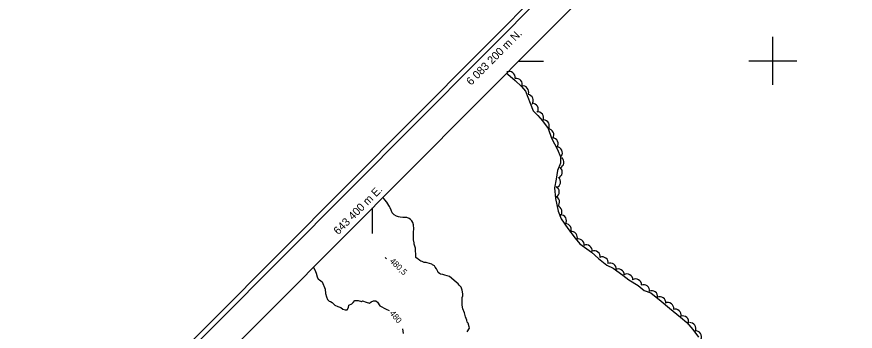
# Model space of a CAD drawing. Extents: x 642515 to 647219, y 6080136 to 6084356.
# Drawn here: x 643222.3 to 643641.3, y 6083064.9 to 6083222.3 of the extents above; entities that cross this region are included whole.
import ezdxf

# ---------------------------------------------------------------- set-up
doc = ezdxf.new("R2010")
doc.units = 0
for name, color, linetype in [('Level 1', 7, 'Continuous'), ('Level 3', 7, 'Continuous'), ('Level 4', 7, 'Continuous'), ('Level 44', 7, 'Continuous'), ('Level 60', 7, 'Continuous'), ('Level 61', 7, 'Continuous')]:
    doc.layers.add(name, color=color, linetype=linetype)

msp = doc.modelspace()

# ---------------------------------------------------------------- linework, layer by layer
at = {"layer": 'Level 1'}
for points in [[(643432.93, 6083094.31), (643432.66, 6083094.86), (643432.03, 6083096.06), (643431.42, 6083096.92), (643430.98, 6083097.64), (643430.06, 6083098.16), (643429.64, 6083098.39), (643427.4, 6083099.17), (643426.82, 6083099.23), (643425.84, 6083099.34), (643424.84, 6083099.78), (643424.26, 6083100), (643423.75, 6083100.3), (643422.82, 6083100.99), (643422.32, 6083101.29), (643421.72, 6083101.83), (643421.64, 6083103.62), (643421.58, 6083104.93), (643421.51, 6083106.39), (643420.93, 6083108.49), (643420.9, 6083109.14), (643420.58, 6083110.68), (643420.49, 6083112.63), (643420.58, 6083114.43), (643420.67, 6083116.07), (643420.49, 6083118.1), (643420.28, 6083119.23), (643419.66, 6083120.1), (643418.98, 6083120.72), (643418.39, 6083121.26), (643417.14, 6083121.77), (643415.17, 6083121.84), (643413.86, 6083121.94), (643413.04, 6083122.06), (643412.04, 6083122.5), (643410.94, 6083123.18), (643409.92, 6083124.11), (643409.45, 6083125.48), (643408.91, 6083126.6), (643408.55, 6083127.23), (643408.28, 6083127.79), (643407.15, 6083129.45), (643406.19, 6083130.63), (643405.75, 6083131.34), (643405.18, 6083131.86)], [(643370.55, 6083097.02), (643370.64, 6083096.85), (643371.27, 6083095.66), (643371.84, 6083093.89), (643372.41, 6083092.13), (643372.95, 6083091.01), (643373.63, 6083090.55), (643374.98, 6083089.64), (643376.38, 6083085.87), (643376.64, 6083083.76), (643377.04, 6083082.15), (643377.59, 6083080.71), (643378.36, 6083080.01), (643379.03, 6083079.72), (643379.95, 6083079.2), (643380.63, 6083078.58), (643381.31, 6083077.96), (643382.73, 6083077.29), (643384.23, 6083076.71), (643385.25, 6083075.95), (643386.41, 6083075.52), (643387.46, 6083075.65), (643387.99, 6083076.74), (643388.18, 6083077.97), (643389.78, 6083078.54), (643390.4, 6083079.22), (643391.25, 6083080.33), (643391.58, 6083080.34), (643392.89, 6083080.24), (643394.54, 6083079.84), (643395.1, 6083080.11), (643396.85, 6083079.46), (643398.58, 6083078.98), (643399.45, 6083079.59), (643400.5, 6083080.05), (643401.72, 6083080.03), (643402.57, 6083079.42), (643403.79, 6083077.68), (643406.89, 6083075.96), (643408.31, 6083075.23)], [(643447.42, 6083064.59), (643448.57, 6083066.36), (643448.37, 6083067.16), (643447.8, 6083068.93), (643447.36, 6083069.48), (643447.24, 6083070.37), (643446.51, 6083072.13), (643446.01, 6083074.14), (643445.18, 6083076.14), (643444.94, 6083077.93), (643444.85, 6083081.76), (643445.14, 6083082.59), (643445.26, 6083083.57), (643444.84, 6083085.51), (643444.37, 6083086.87), (643443.43, 6083087.89), (643442.82, 6083088.59), (643441.89, 6083089.44), (643441.89, 6083089.44), (643438.57, 6083092.3), (643436.25, 6083093), (643435.26, 6083093.28), (643434.11, 6083093.38), (643433.52, 6083093.76), (643432.93, 6083094.31)], [(643415.03, 6083066.11), (643415.45, 6083063.82)]]:
    msp.add_lwpolyline(points, dxfattribs=at)
at = {"layer": 'Level 3'}
msp.add_line((643406.41, 6083101.75), (643406.98, 6083101.19), dxfattribs=at)
at = {"layer": 'Level 4'}
msp.add_lwpolyline([(643467.01, 6083194.07), (643467.76, 6083193.48), (643471.34, 6083190.3), (643474.58, 6083187.35), (643476.47, 6083185), (643478.92, 6083178.99), (643480.42, 6083175.25), (643482.72, 6083172.92), (643485.09, 6083170.14), (643487.87, 6083166.34), (643489.47, 6083161.5), (643492.6, 6083155.81), (643494.11, 6083152.08), (643494.06, 6083149.06), (643492.56, 6083145.3), (643491.88, 6083140.96), (643490.98, 6083136.66), (643491.51, 6083131.23), (643492.93, 6083125.05), (643494.41, 6083121.11), (643497.77, 6083116.32), (643501.35, 6083111.41), (643503.72, 6083108.55), (643509.56, 6083104.41), (643513, 6083101.28), (643517.11, 6083098.01), (643520.36, 6083096.39), (643525.13, 6083092.99), (643528.21, 6083090.58), (643532.87, 6083087.75), (643535.88, 6083085.25), (643539.1, 6083084.05), (643544.27, 6083079.97), (643548.56, 6083076.46), (643554, 6083071.98), (643557.09, 6083069.24), (643560.23, 6083065.68), (643562.96, 6083061.85)], dxfattribs=at)
at = {"layer": 'Level 44'}
for centre, start, end in [((643468.34, 6083191.84), 352.1089, 112.0868), ((643471.92, 6083188.44), 340.3666, 100.3446), ((643475.16, 6083184.63), 340.3666, 100.3446), ((643477.45, 6083180.34), 323.2525, 83.2305), ((643479.89, 6083175.94), 330.5221, 90.5), ((643482.59, 6083171.7), 337.4121, 97.39), ((643485.45, 6083167.68), 326.8546, 86.8325), ((643487.7, 6083163.22), 326.8546, 86.8325), ((643489.86, 6083158.72), 325.0958, 85.0737), ((643491.98, 6083154.19), 325.0958, 85.0737), ((643492.73, 6083149.45), 291.1916, 51.1695), ((643491.95, 6083144.52), 289.4418, 49.4198), ((643491.03, 6083139.61), 289.4418, 49.4198), ((643490.41, 6083134.61), 300.6641, 60.642), ((643490.54, 6083129.55), 313.9423, 73.9202), ((643491.74, 6083124.69), 313.9423, 73.9202), ((643494.01, 6083120.17), 328.8961, 88.874), ((643496.42, 6083115.79), 328.8961, 88.874), ((643499.48, 6083111.79), 339.3664, 99.3444), ((643502.89, 6083108.06), 353.7121, 113.6901), ((643506.92, 6083105.1), 353.7121, 113.6901), ((643510.93, 6083102.13), 352.604, 112.582), ((643514.9, 6083099.09), 352.604, 112.582), ((643518.87, 6083096.05), 352.604, 112.582), ((643522.9, 6083093.03), 0.0208, 119.9988), ((643527.23, 6083090.53), 0.0208, 119.9988), ((643531.56, 6083088.03), 0.0208, 119.9988), ((643535.6, 6083085.15), 353.4576, 113.4356), ((643539.61, 6083082.17), 353.4576, 113.4356), ((643543.64, 6083079.2), 353.8505, 113.8285), ((643547.67, 6083076.24), 353.8505, 113.8285), ((643551.38, 6083072.94), 347.7449, 107.7229), ((643555.08, 6083069.58), 347.7449, 107.7229), ((643558.67, 6083066.22), 334.276, 94.254), ((643561.49, 6083062.09), 334.276, 94.254)]:
    msp.add_arc(centre, 3, start, end, dxfattribs=at)
at = {"layer": 'Level 60'}
for p, q in [((643472.83, 6083200), (643485.6, 6083200)), ((643400, 6083113.78), (643400, 6083126.64))]:
    msp.add_line(p, q, dxfattribs=at)
for points in [[(643756.15, 6083509.1), (645893.11, 6081385.05), (644652.25, 6080135.58), (642514.75, 6082260.08)], [(642518.29, 6082260.09), (643756.16, 6083505.56), (645889.57, 6081385.04), (644651.74, 6080139.63)], [(643756.23, 6083485.06), (645517.55, 6081734.46), (644300.6, 6080509.08), (642538.79, 6082260.16)]]:
    msp.add_lwpolyline(points, close=True, dxfattribs=at)
at = {"layer": 'Level 61'}
for p, q in [((643600, 6083212.16), (643600, 6083188.16)), ((643612.16, 6083200), (643588.16, 6083200))]:
    msp.add_line(p, q, dxfattribs=at)

# ---------------------------------------------------------------- texts
at = {"layer": 'Level 1'}
msp.add_text('480', height=3, rotation=309.394, dxfattribs=at).set_placement((643408.43, 6083073.76))
at = {"layer": 'Level 3'}
msp.add_text('480,5', height=3, rotation=315.59, dxfattribs=at).set_placement((643408.44, 6083099.71))
at = {"layer": 'Level 61'}
for s, p in [('6 083 200 m N.', (643449.33, 6083187.64)), ('643 400 m E.', (643382.94, 6083112.89))]:
    msp.add_text(s, height=4, rotation=45.175, dxfattribs=at).set_placement(p)

doc.saveas('drawing.dxf')
